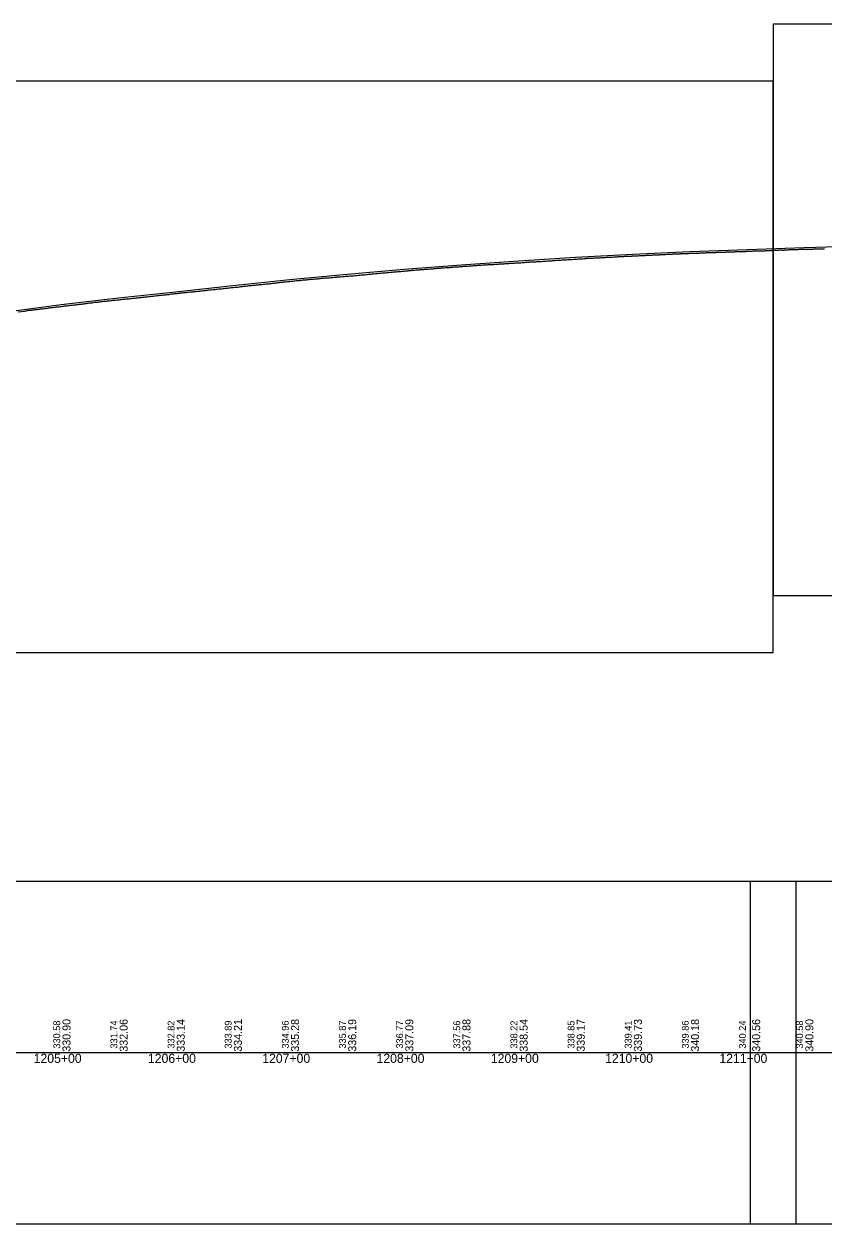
# Model space of a CAD drawing. Extents: x 2898 to 49495, y -15038 to -13538.
# Drawn here: x 9821 to 10521, y -15038 to -13988 of the extents above; entities that cross this region are included whole.
import ezdxf

# ---------------------------------------------------------------- set-up
doc = ezdxf.new("R2010")
doc.units = 0
for name, color, linetype in [('RD_DDB_Profile_EX', 7, 'Continuous'), ('RD_DDB_Profile_PR', 7, 'Continuous'), ('RD_DDB_StaTX', 7, 'Continuous'), ('RD_DDB_StripGrade', 7, 'Continuous'), ('RD_GPK_Profile_Cell', 7, 'Continuous'), ('RD_SHT_ShtClip', 7, 'Continuous')]:
    doc.layers.add(name, color=color, linetype=linetype)

msp = doc.modelspace()

# ---------------------------------------------------------------- linework, layer by layer
at = {"layer": 'RD_DDB_Profile_EX'}
for points in [[(10492.2, -14185.9), (10492.8, -14185.9), (10493.2, -14185.9), (10494.1, -14185.8), (10494.8, -14185.8), (10495.1, -14185.8), (10495.8, -14185.8), (10496.1, -14185.8), (10496.8, -14185.8), (10497.1, -14185.8), (10497.8, -14185.7), (10498.1, -14185.7), (10499.1, -14185.6), (10499.8, -14185.6), (10500.1, -14185.6), (10500.8, -14185.6), (10501.1, -14185.6), (10501.8, -14185.6), (10502.1, -14185.6), (10502.8, -14185.6), (10503.1, -14185.6), (10503.8, -14185.6), (10504.1, -14185.6), (10504.5, -14185.6), (10504.9, -14185.6), (10505.5, -14185.6), (10505.9, -14185.5), (10506.5, -14185.5), (10506.9, -14185.5), (10507.5, -14185.5), (10507.9, -14185.4), (10508.9, -14185.4), (10509.5, -14185.4), (10509.9, -14185.4), (10510.5, -14185.4), (10510.9, -14185.4), (10511.5, -14185.3), (10511.9, -14185.3), (10512.5, -14185.3), (10512.9, -14185.3), (10513.5, -14185.3), (10513.9, -14185.3), (10514.5, -14185.3), (10514.9, -14185.2), (10515.5, -14185.2), (10515.9, -14185.2), (10516.5, -14185.2), (10516.9, -14185.2), (10517.5, -14185.1), (10517.9, -14185.1), (10518.2, -14185.1), (10518.5, -14185.1), (10518.9, -14185.1), (10519.7, -14185.1), (10520.3, -14185.1), (10520.7, -14185.1), (10521.3, -14185.1)], [(10203.4, -14200.7), (10204.4, -14200.6), (10205.4, -14200.5), (10206.4, -14200.4), (10207.4, -14200.3), (10208.4, -14200.3), (10209.4, -14200.3), (10210.4, -14200.2), (10211.4, -14200.1), (10212.4, -14200), (10213.4, -14200), (10214.4, -14199.9), (10214.8, -14199.8), (10215.4, -14199.8), (10215.9, -14199.8), (10216.9, -14199.7), (10217.9, -14199.6), (10218.9, -14199.6), (10219.9, -14199.5), (10220.9, -14199.4), (10221.9, -14199.3), (10222.9, -14199.2), (10223.9, -14199.2), (10224.9, -14199.1), (10225.9, -14199.1), (10226.9, -14199), (10227.9, -14199), (10228.9, -14198.9), (10229.3, -14198.9), (10229.9, -14198.9), (10230.9, -14198.8), (10231.9, -14198.8), (10232.9, -14198.7), (10234.1, -14198.6), (10234.9, -14198.5), (10235.9, -14198.5), (10236.9, -14198.4), (10237.9, -14198.3), (10238.9, -14198.3), (10239.9, -14198.3), (10240.9, -14198.2), (10241.9, -14198.1), (10242.9, -14198), (10243.9, -14197.9), (10244.9, -14197.9), (10245.9, -14197.8), (10246.9, -14197.8), (10247.9, -14197.7), (10248.9, -14197.7), (10249.9, -14197.6), (10250.9, -14197.5), (10251.9, -14197.5), (10252.6, -14197.4), (10253.6, -14197.3), (10254.6, -14197.3), (10255.6, -14197.3), (10256.6, -14197.2), (10257.6, -14197.2), (10258.6, -14197.1), (10259.6, -14197), (10260.6, -14196.9), (10261.6, -14196.8), (10262.6, -14196.8), (10263, -14196.7), (10263.6, -14196.7), (10264.6, -14196.7), (10265.6, -14196.6), (10266.6, -14196.5), (10267.8, -14196.5), (10268.6, -14196.5), (10269.6, -14196.4), (10270.6, -14196.3), (10271.6, -14196.2), (10272.6, -14196.2), (10273.6, -14196.2), (10274.6, -14196.1), (10275.6, -14196), (10276.6, -14195.9), (10277.7, -14195.9), (10278.7, -14195.8), (10279.7, -14195.7), (10280.7, -14195.6), (10281.7, -14195.6), (10282.7, -14195.6), (10283.6, -14195.5), (10284.6, -14195.4), (10285.5, -14195.3), (10286.5, -14195.2), (10287.5, -14195.1), (10288.5, -14195.1), (10289.5, -14195.1), (10290.5, -14195), (10291.5, -14194.9), (10291.9, -14194.9), (10292.5, -14194.8), (10293.5, -14194.8), (10294.5, -14194.7), (10295.5, -14194.7), (10296.7, -14194.6), (10297.5, -14194.6), (10298.5, -14194.5)], [(10298.5, -14194.5), (10299.5, -14194.4), (10300.5, -14194.4), (10301.5, -14194.3), (10302.5, -14194.3), (10303.5, -14194.2), (10304.5, -14194.1), (10305.5, -14194), (10306.5, -14194), (10307.5, -14193.9), (10308.5, -14193.8), (10309.5, -14193.8), (10310.5, -14193.7), (10311.5, -14193.6), (10312.5, -14193.6), (10313.5, -14193.5), (10314.4, -14193.5), (10315.4, -14193.4), (10316.4, -14193.4), (10317.4, -14193.4), (10318.8, -14193.3), (10319.8, -14193.2), (10320.8, -14193.2), (10321.8, -14193.2), (10322.8, -14193.1), (10323.8, -14193), (10324.8, -14193), (10325.8, -14192.9), (10326.8, -14192.9), (10327.8, -14192.8), (10328.8, -14192.8), (10329.8, -14192.7), (10330.8, -14192.6), (10331.8, -14192.6), (10332.8, -14192.5), (10333.8, -14192.5), (10334.8, -14192.4), (10335.2, -14192.4), (10335.8, -14192.4), (10336.8, -14192.3), (10337.8, -14192.3), (10338.8, -14192.3), (10340, -14192.1), (10340.8, -14192), (10341.8, -14192), (10342.8, -14192), (10343.6, -14191.9), (10344.8, -14191.9), (10345.6, -14191.8), (10346.6, -14191.7), (10347.6, -14191.7), (10348.6, -14191.7), (10350.2, -14191.6), (10351.2, -14191.5), (10352.2, -14191.5), (10353.2, -14191.4), (10354.2, -14191.4), (10354.5, -14191.3), (10355.2, -14191.3), (10356.2, -14191.3), (10357.2, -14191.2), (10358.2, -14191.2), (10359.3, -14191.1), (10360.2, -14191), (10361.2, -14191), (10362.2, -14191), (10363.2, -14190.9), (10364.2, -14190.9), (10365.2, -14190.8), (10366.2, -14190.8), (10367.2, -14190.8), (10368, -14190.7), (10369, -14190.7), (10370, -14190.6), (10371, -14190.5), (10372, -14190.5), (10373, -14190.5), (10374, -14190.5), (10375, -14190.4), (10376, -14190.3), (10377, -14190.3), (10378, -14190.2), (10379, -14190.2), (10380, -14190.2), (10381, -14190.1), (10382.1, -14190.1), (10383.4, -14190), (10384.1, -14189.9), (10385.1, -14189.9), (10385.8, -14189.9), (10386.1, -14189.8), (10386.8, -14189.8), (10387.1, -14189.8), (10387.8, -14189.8), (10388.2, -14189.8), (10388.8, -14189.7), (10389.1, -14189.7), (10389.8, -14189.7), (10390.1, -14189.7), (10390.8, -14189.6), (10391.1, -14189.6)], [(10391.1, -14189.6), (10391.8, -14189.6), (10392.1, -14189.6), (10393.1, -14189.6), (10393.8, -14189.6), (10394.1, -14189.5), (10394.8, -14189.5), (10395.1, -14189.5), (10395.8, -14189.4), (10396.2, -14189.4), (10396.9, -14189.4), (10397.2, -14189.3), (10397.9, -14189.3), (10398.2, -14189.3), (10398.9, -14189.3), (10399.2, -14189.3), (10399.9, -14189.3), (10400.2, -14189.3), (10400.9, -14189.2), (10401.2, -14189.2), (10401.9, -14189.2), (10402.2, -14189.2), (10402.9, -14189.1), (10403.2, -14189.2), (10403.9, -14189.1), (10404.2, -14189.1), (10404.9, -14189.1), (10405.2, -14189), (10405.9, -14189), (10406.2, -14189), (10406.9, -14189), (10407.4, -14188.9), (10407.9, -14188.9), (10408.2, -14188.9), (10408.9, -14188.9), (10409.2, -14188.9), (10409.9, -14188.9), (10410.2, -14188.9), (10410.9, -14188.9), (10411.2, -14188.9), (10411.9, -14188.9), (10412.3, -14188.8), (10412.8, -14188.7), (10413.1, -14188.7), (10413.8, -14188.7), (10414.1, -14188.7), (10414.8, -14188.7), (10415.1, -14188.7), (10415.8, -14188.7), (10416.1, -14188.6), (10417.1, -14188.6), (10417.8, -14188.5), (10418.1, -14188.5), (10418.8, -14188.5), (10419.1, -14188.5), (10419.8, -14188.4), (10420.1, -14188.4), (10420.8, -14188.4), (10421.1, -14188.4), (10421.9, -14188.4), (10422.5, -14188.4), (10422.8, -14188.4), (10423.2, -14188.4), (10423.8, -14188.3), (10424.2, -14188.3), (10424.8, -14188.3), (10425.2, -14188.3), (10425.8, -14188.3), (10426.2, -14188.3), (10426.8, -14188.2), (10427.2, -14188.2), (10427.8, -14188.2), (10428.2, -14188.2), (10428.8, -14188.2), (10429.5, -14188.1), (10429.8, -14188.1), (10430.2, -14188.1), (10430.8, -14188.1), (10431.2, -14188.1), (10431.5, -14188.1), (10431.8, -14188), (10432.2, -14188), (10432.8, -14188), (10433.2, -14188), (10433.8, -14188), (10434.2, -14188), (10434.8, -14188), (10435.2, -14188), (10435.8, -14187.9), (10436.3, -14187.9), (10436.8, -14187.9), (10437.2, -14188), (10437.8, -14187.9), (10438.2, -14187.9), (10438.8, -14187.9), (10439.2, -14187.8), (10439.8, -14187.8), (10440.2, -14187.8), (10440.8, -14187.7), (10441.2, -14187.7), (10441.8, -14187.7)], [(10441.8, -14187.7), (10442.2, -14187.7), (10442.8, -14187.7), (10443.2, -14187.6), (10443.8, -14187.6), (10444.3, -14187.6), (10444.7, -14187.6), (10445.3, -14187.6), (10446, -14187.6), (10446.3, -14187.5), (10446.7, -14187.5), (10447.3, -14187.5), (10447.7, -14187.5), (10448.3, -14187.4), (10448.8, -14187.4), (10449.4, -14187.4), (10449.8, -14187.4), (10450.4, -14187.4), (10450.8, -14187.4), (10451.4, -14187.4), (10451.8, -14187.4), (10452.4, -14187.4), (10452.8, -14187.3), (10453.4, -14187.3), (10453.8, -14187.3), (10454.4, -14187.2), (10454.8, -14187.2), (10455.8, -14187.1), (10456.4, -14187.1), (10456.8, -14187.1), (10457.4, -14187.1), (10457.8, -14187.1), (10458.4, -14187), (10458.8, -14187), (10459.4, -14187), (10459.8, -14187), (10460.4, -14187), (10460.8, -14187), (10461.4, -14187), (10461.8, -14187), (10462.4, -14186.9), (10462.8, -14186.9), (10463.4, -14186.9), (10463.8, -14186.9), (10464.4, -14186.9), (10464.8, -14186.9), (10465.4, -14186.8), (10465.8, -14186.8), (10466.4, -14186.8), (10466.8, -14186.8), (10467.4, -14186.8), (10467.8, -14186.8), (10468.4, -14186.8), (10468.8, -14186.8), (10469.6, -14186.7), (10470, -14186.7), (10470.6, -14186.7), (10470.9, -14186.7), (10471.8, -14186.7), (10472.2, -14186.6), (10472.8, -14186.6), (10473.2, -14186.6), (10473.8, -14186.6), (10474.2, -14186.6), (10474.9, -14186.6), (10475.2, -14186.5), (10475.8, -14186.5), (10476.2, -14186.5), (10476.8, -14186.4), (10477.2, -14186.4), (10477.8, -14186.4), (10478.2, -14186.4), (10478.8, -14186.4), (10479.2, -14186.4), (10479.8, -14186.4), (10480.2, -14186.3), (10480.8, -14186.3), (10481.2, -14186.3), (10481.8, -14186.2), (10482.2, -14186.2), (10482.8, -14186.2), (10483.2, -14186.2), (10483.8, -14186.2), (10484.2, -14186.3), (10484.5, -14186.3), (10484.8, -14186.3), (10485.2, -14186.3), (10485.8, -14186.3), (10486.2, -14186.2), (10486.8, -14186.1), (10487.2, -14186.1), (10487.8, -14186.1), (10488.2, -14186), (10488.8, -14186), (10489.3, -14186), (10489.8, -14186), (10490.2, -14185.9), (10490.8, -14185.9), (10491.2, -14185.9), (10491.8, -14185.9), (10492.2, -14185.9)], [(10111, -14208.5), (10112, -14208.4), (10113, -14208.3), (10113.7, -14208.2), (10114, -14208.2), (10115, -14208.1), (10116, -14208), (10117, -14207.9), (10118.1, -14207.9), (10118.5, -14207.8), (10119.1, -14207.8), (10120.1, -14207.7), (10121.1, -14207.6), (10122.1, -14207.5), (10123.3, -14207.4), (10124.1, -14207.3), (10125.1, -14207.2), (10126.1, -14207.1), (10127.1, -14207), (10128.2, -14206.9), (10129.1, -14206.8), (10130.1, -14206.7), (10131.1, -14206.6), (10132.1, -14206.5), (10133.1, -14206.5), (10134.1, -14206.3), (10135.1, -14206.2), (10136.1, -14206.2), (10137.1, -14206.1), (10138.1, -14206), (10139.1, -14205.9), (10140.1, -14205.8), (10141.1, -14205.7), (10142.1, -14205.6), (10142.6, -14205.6), (10143.2, -14205.5), (10144, -14205.4), (10144.6, -14205.4), (10145.5, -14205.3), (10146.5, -14205.2), (10147.5, -14205.1), (10148.5, -14205.1), (10149.5, -14205), (10150.5, -14204.9), (10151.5, -14204.7), (10152.5, -14204.7), (10153.5, -14204.6), (10154.5, -14204.5), (10155.5, -14204.4), (10156.5, -14204.3), (10157, -14204.3), (10157.5, -14204.2), (10158.5, -14204.2), (10159.5, -14204.1), (10160.5, -14204), (10161.5, -14203.9), (10161.9, -14203.9), (10162.5, -14203.8), (10163.5, -14203.7), (10164.5, -14203.6), (10165.5, -14203.6), (10166.7, -14203.5), (10167.5, -14203.4), (10168.5, -14203.4), (10169.5, -14203.3), (10170.5, -14203.2), (10171.5, -14203.1), (10172.7, -14203), (10173.6, -14202.9), (10174.7, -14202.9), (10175.7, -14202.7), (10176.7, -14202.6), (10177.7, -14202.6), (10178.7, -14202.6), (10179.7, -14202.5), (10180.7, -14202.3), (10181.1, -14202.3), (10181.7, -14202.2), (10182.7, -14202.2), (10183.5, -14202.1), (10184.5, -14202), (10185.5, -14202), (10185.9, -14201.9), (10186.5, -14201.9), (10187.5, -14201.9), (10188.5, -14201.7), (10189.5, -14201.6), (10190.8, -14201.5), (10191.5, -14201.5), (10192.5, -14201.4), (10193.5, -14201.4), (10194.5, -14201.3), (10195.6, -14201.2), (10196.5, -14201.1), (10197.5, -14201), (10198.5, -14201), (10199.5, -14201), (10200.5, -14200.8), (10201.5, -14200.8), (10202.5, -14200.7), (10203.4, -14200.7)], [(10012.9, -14218), (10013.9, -14218), (10014.9, -14217.8), (10015.9, -14217.7), (10016.9, -14217.6), (10017.9, -14217.4), (10018.9, -14217.4), (10019.9, -14217.2), (10020.9, -14217.1), (10021.9, -14217), (10022.9, -14216.9), (10023.9, -14216.7), (10024.9, -14216.7), (10025.9, -14216.6), (10026.9, -14216.5), (10027.9, -14216.4), (10028.9, -14216.3), (10029.9, -14216.1), (10031.2, -14216), (10032.2, -14215.9), (10033.2, -14215.9), (10034.2, -14215.8), (10035.2, -14215.7), (10036.2, -14215.6), (10037.2, -14215.4), (10038.2, -14215.3), (10039.2, -14215.2), (10040.2, -14215.1), (10041.2, -14215), (10042.2, -14214.8), (10043.2, -14214.7), (10044.2, -14214.7), (10045.2, -14214.5), (10046.2, -14214.5), (10047.2, -14214.3), (10048.2, -14214.2), (10049.2, -14214.2), (10050.2, -14214), (10051.2, -14213.9), (10052.1, -14213.8), (10053.2, -14213.7), (10054.1, -14213.6), (10055.2, -14213.5), (10056.1, -14213.4), (10057.1, -14213.3), (10058.1, -14213.1), (10059.1, -14213), (10060.1, -14213), (10061.1, -14212.9), (10062.1, -14212.8), (10063.1, -14212.7), (10064.1, -14212.5), (10065.1, -14212.4), (10066.1, -14212.3), (10067.1, -14212.2), (10068.1, -14212.2), (10069.1, -14212.1), (10070.4, -14211.9), (10071.2, -14211.8), (10072.1, -14211.8), (10073.1, -14211.7), (10074.1, -14211.6), (10075.2, -14211.5), (10076.1, -14211.4), (10077.1, -14211.4), (10078.1, -14211.3), (10079.1, -14211.2), (10080.1, -14211.1), (10081.1, -14211), (10082.1, -14211), (10083.1, -14210.9), (10084.1, -14210.7), (10085.1, -14210.7), (10086.1, -14210.6), (10087.1, -14210.5), (10088.1, -14210.5), (10089.1, -14210.3), (10089.6, -14210.3), (10090.1, -14210.3), (10091.1, -14210.2), (10092.1, -14210.1), (10093.1, -14210), (10094.1, -14209.9), (10094.4, -14209.8), (10095.1, -14209.8), (10096.1, -14209.7), (10097.1, -14209.7), (10098.1, -14209.6), (10099.3, -14209.5), (10100.1, -14209.4), (10101.1, -14209.3), (10102.1, -14209.2), (10103.1, -14209.1), (10104.1, -14209.1), (10105.1, -14209), (10106.1, -14208.9), (10107.1, -14208.9), (10108.1, -14208.8), (10109.1, -14208.7), (10110.1, -14208.6), (10111, -14208.5)], [(9912.9, -14228.8), (9913.9, -14228.7), (9914.9, -14228.6), (9915.9, -14228.5), (9916.9, -14228.4), (9917.9, -14228.3), (9918.9, -14228.1), (9919.9, -14228.1), (9920.9, -14228), (9921.9, -14227.9), (9922.9, -14227.8), (9923.9, -14227.6), (9924.9, -14227.5), (9925.9, -14227.4), (9926.9, -14227.3), (9927.9, -14227.1), (9928.9, -14227.1), (9929.9, -14227), (9930.9, -14226.8), (9931.9, -14226.7), (9932.9, -14226.6), (9933.9, -14226.5), (9934.9, -14226.4), (9935.9, -14226.2), (9936.9, -14226.1), (9937.9, -14226), (9938.7, -14225.9), (9939.7, -14225.8), (9940.7, -14225.7), (9941.7, -14225.6), (9942.7, -14225.5), (9943.7, -14225.4), (9944.7, -14225.3), (9945.7, -14225.2), (9946.7, -14225.1), (9947.7, -14225.1), (9948.7, -14224.8), (9949.7, -14224.7), (9950.7, -14224.6), (9951.7, -14224.5), (9952.7, -14224.4), (9953.7, -14224.3), (9954.7, -14224.3), (9955.7, -14224.1), (9956.7, -14223.9), (9957.7, -14223.8), (9958.7, -14223.8), (9959.7, -14223.6), (9960.7, -14223.5), (9961.7, -14223.4), (9962.7, -14223.3), (9963.7, -14223.2), (9964.7, -14223.1), (9965.7, -14222.9), (9966.7, -14222.9), (9967.7, -14222.8), (9968.7, -14222.7), (9969.7, -14222.6), (9970.7, -14222.5), (9971.7, -14222.4), (9972.7, -14222.3), (9973.5, -14222.2), (9974.5, -14222.1), (9975.5, -14222), (9976.5, -14221.8), (9977.7, -14221.7), (9978.5, -14221.7), (9979.5, -14221.6), (9980.5, -14221.4), (9981.5, -14221.3), (9982.5, -14221.2), (9983.5, -14221.1), (9984.5, -14221.1), (9986, -14220.9), (9986.9, -14220.8), (9987.9, -14220.7), (9988.9, -14220.6), (9989.9, -14220.5), (9990.9, -14220.3), (9991.9, -14220.2), (9992.9, -14220.1), (9993.9, -14220.1), (9994.9, -14219.9), (9995.9, -14219.8), (9996.9, -14219.7), (9997.9, -14219.6), (9998.9, -14219.5), (9999.9, -14219.4), (10000.9, -14219.3), (10001.9, -14219.1), (10002.9, -14219), (10003.9, -14219), (10004.9, -14218.8), (10005.9, -14218.8), (10006.9, -14218.7), (10007.9, -14218.6), (10008.9, -14218.4), (10009.9, -14218.3), (10010.9, -14218.2), (10011.9, -14218.1), (10012.9, -14218)], [(9815.7, -14240.4), (9821.4, -14239.7), (9822.2, -14239.5), (9823, -14239.3), (9823.8, -14239.2), (9824.7, -14239), (9825.5, -14239), (9826.3, -14238.9), (9827.3, -14238.9), (9828.3, -14238.7), (9829.3, -14238.6), (9830.3, -14238.4), (9831.3, -14238.3), (9832.3, -14238.2), (9833.3, -14238), (9834.3, -14238), (9835.3, -14237.8), (9836.3, -14237.6), (9837.3, -14237.6), (9838.3, -14237.4), (9839.3, -14237.3), (9840.3, -14237.1), (9841.3, -14237), (9842.3, -14236.9), (9843.3, -14236.8), (9844.3, -14236.6), (9845.3, -14236.5), (9846.3, -14236.4), (9847.3, -14236.3), (9848.3, -14236.2), (9849.3, -14236), (9850.3, -14235.9), (9851.3, -14235.8), (9852.3, -14235.7), (9853.3, -14235.6), (9854.3, -14235.5), (9855.3, -14235.3), (9856.3, -14235.2), (9857.3, -14235.1), (9858.3, -14235), (9859.3, -14234.9), (9860.3, -14234.8), (9861.3, -14234.6), (9862.3, -14234.5), (9863.3, -14234.4), (9864.3, -14234.3), (9865.3, -14234.2), (9866.3, -14234.1), (9867.3, -14234), (9868.3, -14233.8), (9869.3, -14233.7), (9870.3, -14233.6), (9871.3, -14233.5), (9872.3, -14233.3), (9873.3, -14233.2), (9874.3, -14233), (9875.3, -14232.9), (9876.3, -14232.8), (9877.3, -14232.6), (9878.3, -14232.5), (9879.3, -14232.4), (9880.3, -14232.3), (9881.3, -14232.2), (9882.3, -14232), (9883.3, -14231.9), (9884.3, -14231.8), (9885.3, -14231.8), (9886.3, -14231.7), (9887.3, -14231.5), (9888.2, -14231.4), (9889.2, -14231.2), (9890.2, -14231.1), (9891.2, -14231.1), (9891.9, -14231), (9892.9, -14230.9), (9893.9, -14230.7), (9894.9, -14230.6), (9895.9, -14230.6), (9896.9, -14230.4), (9897.9, -14230.4), (9898.9, -14230.2), (9899.9, -14230.1), (9900.9, -14230), (9901.9, -14229.9), (9902.9, -14229.8), (9903.9, -14229.7), (9904.9, -14229.6), (9905.9, -14229.4), (9906.9, -14229.3), (9907.9, -14229.2), (9908.9, -14229.1), (9909.9, -14229), (9910.9, -14229), (9911.9, -14228.8), (9912.9, -14228.8)]]:
    msp.add_lwpolyline(points, dxfattribs=at)
at = {"layer": 'RD_DDB_Profile_PR'}
for points in [[(9853.4, -14234), (9903.4, -14228.1), (9953.4, -14222.7), (10003.4, -14217.4), (10053.4, -14212.1), (10103.4, -14207.5), (10153.4, -14203), (10203.4, -14199.1), (10253.4, -14195.8), (10303.4, -14192.6), (10353.4, -14189.8), (10403.4, -14187.5), (10453.4, -14185.7), (10503.4, -14184), (10553.4, -14182.6)], [(9803.4, -14240.5), (9853.4, -14234)]]:
    msp.add_lwpolyline(points, dxfattribs=at)
at = {"layer": 'RD_GPK_Profile_Cell'}
msp.add_line((2976.1, -14888.5), (48721.1, -14888.5), dxfattribs=at)
at = {"layer": 'RD_SHT_ShtClip'}
for points in [[(11976.2, -14488.5), (11976.2, -13988.5), (11976.2, -13988.5), (10476.4, -13988.5), (10476.4, -14488.5)], [(10476.2, -14538.5), (10476.2, -14038.5), (10476.2, -14038.5), (8976.4, -14038.5), (8976.4, -14538.5)], [(8956.4, -14738.5), (10496.1, -14738.5), (10496.1, -15038.5), (8956.4, -15038.5)], [(10456.4, -14738.5), (11996.1, -14738.5), (11996.1, -15038.5), (10456.4, -15038.5)]]:
    msp.add_lwpolyline(points, close=True, dxfattribs=at)

# ---------------------------------------------------------------- texts
at = {"layer": 'RD_DDB_StaTX'}
for s, p in [('1205+00', (9829.2, -14897.5)), ('1206+00', (9929.2, -14897.5)), ('1207+00', (10029.2, -14897.5)), ('1208+00', (10129.2, -14897.5)), ('1209+00', (10229.2, -14897.5)), ('1210+00', (10329.2, -14897.5)), ('1211+00', (10429.2, -14897.5))]:
    msp.add_text(s, height=8, dxfattribs=at).set_placement(p)
at = {"layer": 'RD_DDB_StripGrade'}
for s, height, p in [('330.58', 6, (9852.4, -14885)), ('330.90', 7, (9861.4, -14887.7)), ('331.74', 6, (9902.4, -14885)), ('332.06', 7, (9911.4, -14887.7)), ('332.82', 6, (9952.4, -14885)), ('333.14', 7, (9961.4, -14887.7)), ('333.89', 6, (10002.4, -14885)), ('334.21', 7, (10011.4, -14887.7)), ('334.96', 6, (10052.4, -14885)), ('335.28', 7, (10061.4, -14887.7)), ('335.87', 6, (10102.4, -14885)), ('336.19', 7, (10111.4, -14887.7)), ('336.77', 6, (10152.4, -14885)), ('337.09', 7, (10161.4, -14887.7)), ('337.56', 6, (10202.4, -14885)), ('337.88', 7, (10211.4, -14887.7)), ('338.22', 6, (10252.4, -14885)), ('338.54', 7, (10261.4, -14887.7)), ('338.85', 6, (10302.4, -14885)), ('339.17', 7, (10311.4, -14887.7)), ('339.41', 6, (10352.4, -14885)), ('339.73', 7, (10361.4, -14887.7)), ('339.86', 6, (10402.4, -14885)), ('340.18', 7, (10411.4, -14887.7)), ('340.24', 6, (10452.4, -14885)), ('340.56', 7, (10464.9, -14887.7)), ('340.58', 6, (10502.4, -14885)), ('340.90', 7, (10511.4, -14887.7))]:
    msp.add_text(s, height=height, rotation=90, dxfattribs=at).set_placement(p)

doc.saveas('drawing.dxf')
